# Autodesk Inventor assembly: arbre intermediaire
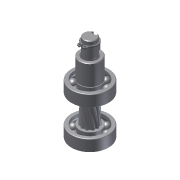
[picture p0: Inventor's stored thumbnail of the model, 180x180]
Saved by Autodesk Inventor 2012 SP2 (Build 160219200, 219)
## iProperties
Created: 2013-04
Part Number: arbre intermediaire
Document SubType Name: Assembly
Designer: papa
Mass: 38.1075 g
Surface Area: 221.352 cm^2
Volume: 38.1075 cm^3
Density: 1 g/cm^3
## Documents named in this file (9)
- F:\Consmec\TBPMSMA\CCF\01-CCF Cermex Moteur\01-02 Dossier Rerssources CERMEX\02-01-04 - Dessins Cermex\02-01-04-01- Dessins 3D Cermex\02-01-04-01-01 - Dessins 3D Motoreducteur\02-01-04-01-01-01 - Composants 3D Motoreducteur R43\arbre intermediaire.iam
- F:\Consmec\TBPMSMA\CCF\01-CCF Cermex Moteur\01-02 Dossier Rerssources CERMEX\02-01-04 - Dessins Cermex\02-01-04-01- Dessins 3D Cermex\02-01-04-01-01 - Dessins 3D Motoreducteur\02-01-04-01-01-01 - Composants 3D Motoreducteur R43\05 - Pignon arbre - Z11.ipt
- F:\Consmec\TBPMSMA\CCF\01-CCF Cermex Moteur\01-02 Dossier Rerssources CERMEX\02-01-04 - Dessins Cermex\02-01-04-01- Dessins 3D Cermex\02-01-04-01-01 - Dessins 3D Motoreducteur\02-01-04-01-01-01 - Composants 3D Motoreducteur R43\roulement 6201.ipt
- F:\Consmec\TBPMSMA\CCF\01-CCF~1\01-02D~1\02-01-~2\02-01-~1\02-01-~1\02-01-~1\entretoise arbre intermediaire.ipt
- F:\Consmec\TBPMSMA\CCF\01-CCF Cermex Moteur\01-02 Dossier Rerssources CERMEX\02-01-04 - Dessins Cermex\02-01-04-01- Dessins 3D Cermex\02-01-04-01-01 - Dessins 3D Motoreducteur\02-01-04-01-01-01 - Composants 3D Motoreducteur R43\clavette _4_4_8.ipt
- F:\Consmec\TBPMSMA\CCF\01-CCF Cermex Moteur\01-02 Dossier Rerssources CERMEX\02-01-04 - Dessins Cermex\02-01-04-01- Dessins 3D Cermex\02-01-04-01-01 - Dessins 3D Motoreducteur\02-01-04-01-01-01 - Composants 3D Motoreducteur R43\02 - Roue entree - Z45.ipt
- F:\Consmec\TBPMSMA\CCF\01-CCF Cermex Moteur\01-02 Dossier Rerssources CERMEX\02-01-04 - Dessins Cermex\02-01-04-01- Dessins 3D Cermex\02-01-04-01-01 - Dessins 3D Motoreducteur\02-01-04-01-01-01 - Composants 3D Motoreducteur R43\anneau elastique 11 x 1.ipt
- F:\Consmec\TBPMSMA\CCF\01-CCF Cermex Moteur\01-02 Dossier Rerssources CERMEX\02-01-04 - Dessins Cermex\02-01-04-01- Dessins 3D Cermex\02-01-04-01-01 - Dessins 3D Motoreducteur\02-01-04-01-01-01 - Composants 3D Motoreducteur R43\anneau elastique 10 x 1.ipt
- F:\Consmec\TBPMSMA\CCF\01-CCF Cermex Moteur\01-02 Dossier Rerssources CERMEX\02-01-04 - Dessins Cermex\02-01-04-01- Dessins 3D Cermex\02-01-04-01-01 - Dessins 3D Motoreducteur\02-01-04-01-01-01 - Composants 3D Motoreducteur R43\rondelle d'epaisseur.ipt
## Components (9 placed, 8 different names)
1. pignon arbre:1 — Placage:1, Placage:2, Placage:3, Logement:1, Logement:5
2. roulement 6201:1 — Logement:1, Logement:2
3. roulement 6201:2 — Logement:5, Logement:6
4. entretoise arbre intermediaire:1 — Logement:2, Logement:3
5. clavette _4_4_8:1 — Placage:1, Placage:2, Placage:3, Placage:4, Angle:1
6. roue entree:1 — Placage:4, Logement:3, Logement:4
7. anneau elastique 11 x 1:1 — Logement:4, Angle:1
8. anneau elastique 10 x 1:4 — Logement:7
9. rondelle d'epaisseur:1 — Logement:6, Logement:7
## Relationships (12: Insert 7, Mate 4, Angle 1)
- Placage:1 [Mate]: pignon arbre:1 ↔ clavette _4_4_8:1
- Placage:2 [Mate]: pignon arbre:1 ↔ clavette _4_4_8:1
- Placage:3 [Mate]: pignon arbre:1 ↔ clavette _4_4_8:1
- Logement:1 [Insert]: pignon arbre:1 ↔ roulement 6201:1
- Logement:2 [Insert]: roulement 6201:1 ↔ entretoise arbre intermediaire:1
- Placage:4 [Mate]: clavette _4_4_8:1 ↔ roue entree:1
- Logement:3 [Insert]: entretoise arbre intermediaire:1 ↔ roue entree:1
- Logement:4 [Insert]: roue entree:1 ↔ anneau elastique 11 x 1:1
- Logement:5 [Insert]: pignon arbre:1 ↔ roulement 6201:2
- Logement:6 [Insert]: roulement 6201:2 ↔ rondelle d'epaisseur:1
- Logement:7 [Insert]: anneau elastique 10 x 1:4 ↔ rondelle d'epaisseur:1
- Angle:1: clavette _4_4_8:1 ↔ anneau elastique 11 x 1:1
